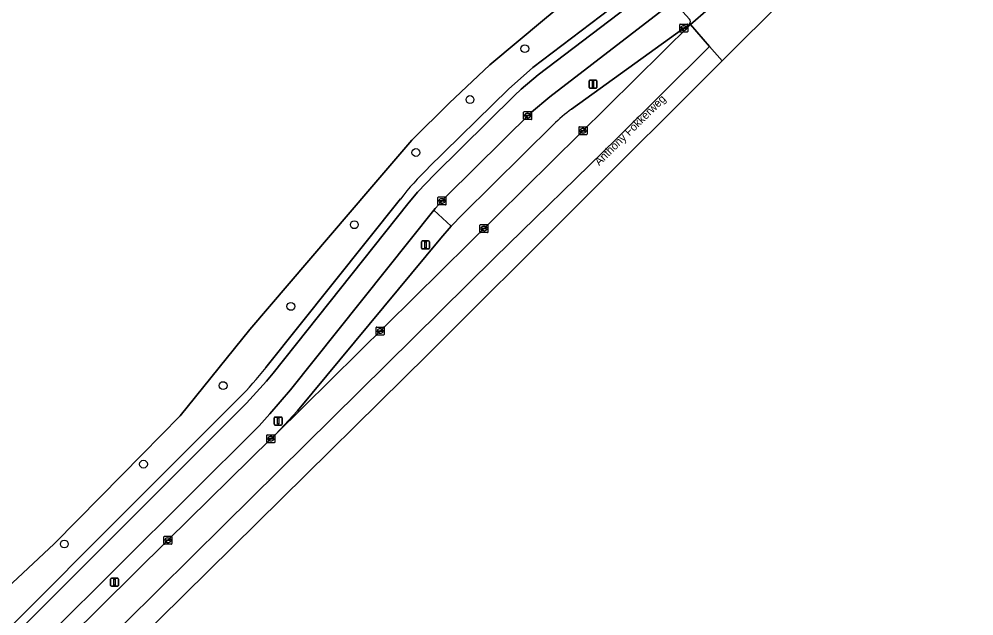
# Model space of a CAD drawing. Extents: x 157320 to 158835, y 386650 to 388491.
# Drawn here: x 158261 to 158380.4, y 386795.4 to 386870.1 of the extents above; entities that cross this region are included whole.
import ezdxf

# ---------------------------------------------------------------- set-up
doc = ezdxf.new("R2010")
doc.units = 0
for name, color, linetype in [('IMGEO_Berm_groen', 7, 'Continuous'), ('IMGEO_Boom', 7, 'Continuous'), ('IMGEO_Bouwland', 7, 'Continuous'), ('IMGEO_Fietspad_gesloten', 7, 'Continuous'), ('IMGEO_Grasland_overig', 7, 'Continuous'), ('IMGEO_Kolk', 7, 'Continuous'), ('IMGEO_Lichtmast', 7, 'Continuous'), ('IMGEO_Openbare_ruimte_label', 7, 'Continuous'), ('IMGEO_OVBaan_open', 7, 'Continuous'), ('IMGEO_Rijbaan_regionaal_gesloten', 7, 'Continuous'), ('IMGEO_Voetpad_open', 7, 'Continuous')]:
    doc.layers.add(name, color=color, linetype=linetype)

msp = doc.modelspace()

# ---------------------------------------------------------------- linework, layer by layer
at = {"layer": 'IMGEO_Berm_groen'}
msp.add_lwpolyline([(158292.51, 386817.6), (158293.08, 386818.13), (158295.82, 386821.08), (158313.75, 386842.66), (158315.04, 386844.17), (158312.86, 386846.16), (158294.96, 386823.72), (158292.37, 386820.71), (158291.06, 386819.23), (158247.07, 386775.47), (158248.3, 386773.88), (158248.45, 386774.04), (158252.57, 386778.18), (158267.21, 386792.63), (158279.64, 386804.91)], close=True, dxfattribs=at)
at = {"layer": 'IMGEO_Boom'}
for centre in [(158324.24, 386866.36), (158317.39, 386860), (158310.63, 386853.38), (158302.94, 386844.35), (158295.01, 386834.14), (158286.54, 386824.24), (158276.59, 386814.42), (158266.69, 386804.43)]:
    msp.add_circle(centre, 0.489, dxfattribs=at)
at = {"layer": 'IMGEO_Bouwland'}
msp.add_lwpolyline([(158181.71, 386843.44), (158180.07, 386842.58), (158234.95, 386779.48), (158235.86, 386778.22), (158242.43, 386783.42), (158246.35, 386786.77), (158250.86, 386790.58), (158258.2, 386797.76), (158265.42, 386804.47), (158271.23, 386810.34), (158276.43, 386815.61), (158281.18, 386820.45), (158289.87, 386831.24), (158304.89, 386848.81), (158310.12, 386854.92), (158314.8, 386859.54), (158319.87, 386864.35), (158326.72, 386870.06), (158334.43, 386876.45), (158305.33, 386908.57)], close=True, dxfattribs=at)
at = {"layer": 'IMGEO_Fietspad_gesloten'}
for points in [[(158339.23, 386873.27), (158325.93, 386863.1), (158323.81, 386861.32), (158322.94, 386860.5), (158312.94, 386850.65), (158310.82, 386848.42), (158309.61, 386846.95), (158292.79, 386825.79), (158291.98, 386824.79), (158289.48, 386822.03), (158246.51, 386779.1)], [(158247.07, 386775.47), (158291.06, 386819.23), (158292.37, 386820.71), (158294.96, 386823.72), (158312.86, 386846.16), (158313.05, 386846.38), (158314.4, 386847.88), (158325.08, 386858.44), (158327.39, 386860.36), (158342.56, 386872.04)]]:
    msp.add_lwpolyline(points, dxfattribs=at)
at = {"layer": 'IMGEO_Grasland_overig'}
for points in [[(158312.15, 386851.45), (158322.2, 386861.32), (158325.26, 386863.99), (158338.55, 386874.13), (158336.73, 386873.92), (158334.43, 386876.45), (158326.72, 386870.06), (158319.87, 386864.35), (158314.8, 386859.54), (158310.12, 386854.92), (158304.89, 386848.81), (158289.87, 386831.24), (158281.18, 386820.45), (158276.43, 386815.61), (158271.23, 386810.34), (158265.42, 386804.47), (158258.2, 386797.76)], [(158291.9, 386826.49), (158308.7, 386847.57)], [(158245.74, 386779.89), (158288.52, 386822.66)]]:
    msp.add_lwpolyline(points, dxfattribs=at)
for centre, radius, start, end in [((158338.86, 386824.25), 38.12, 134.4883, 142.285), ((158254.51, 386856.09), 47.69, 315.4981, 321.6337)]:
    msp.add_arc(centre, radius, start, end, dxfattribs=at)
at = {"layer": 'IMGEO_Kolk'}
for p, q in [((158343.6, 386868.51), (158343.6, 386869.36)), ((158343.68, 386869.44), (158344.53, 386869.44)), ((158344.53, 386868.43), (158343.68, 386868.43)), ((158343.86, 386868.93), (158343.86, 386868.94)), ((158343.9, 386868.98), (158344.3, 386868.98)), ((158344.3, 386868.89), (158343.9, 386868.89)), ((158344.09, 386869.21), (158344.12, 386869.21)), ((158344.11, 386868.66), (158344.09, 386868.66)), ((158344.35, 386868.94), (158344.35, 386868.93)), ((158344.6, 386869.36), (158344.6, 386868.51)), ((158324.1, 386857.57), (158324.1, 386858.42)), ((158324.18, 386858.5), (158325.03, 386858.5)), ((158324.36, 386857.99), (158324.36, 386858)), ((158324.4, 386858.04), (158324.8, 386858.04)), ((158324.8, 386857.95), (158324.4, 386857.95)), ((158324.59, 386858.28), (158324.62, 386858.28)), ((158324.61, 386857.72), (158324.59, 386857.72)), ((158324.85, 386858), (158324.85, 386857.99)), ((158325.1, 386858.42), (158325.1, 386857.57)), ((158325.03, 386857.5), (158324.18, 386857.5)), ((158331.02, 386855.68), (158331.02, 386856.53)), ((158331.09, 386856.6), (158331.95, 386856.6)), ((158332.02, 386856.53), (158332.02, 386855.68)), ((158331.95, 386855.6), (158331.09, 386855.6)), ((158331.28, 386856.1), (158331.28, 386856.11)), ((158331.32, 386856.15), (158331.72, 386856.15)), ((158331.71, 386856.06), (158331.32, 386856.06)), ((158331.53, 386855.82), (158331.5, 386855.82)), ((158331.51, 386856.38), (158331.53, 386856.38)), ((158331.76, 386856.11), (158331.76, 386856.1)), ((158313.39, 386846.9), (158313.39, 386847.75)), ((158313.47, 386847.83), (158314.32, 386847.83)), ((158313.65, 386847.32), (158313.65, 386847.33)), ((158313.69, 386847.37), (158314.09, 386847.37)), ((158314.09, 386847.28), (158313.69, 386847.28)), ((158313.88, 386847.61), (158313.91, 386847.61)), ((158313.9, 386847.05), (158313.88, 386847.05)), ((158314.14, 386847.33), (158314.14, 386847.32)), ((158314.39, 386847.75), (158314.39, 386846.9)), ((158314.32, 386846.83), (158313.47, 386846.83)), ((158318.64, 386843.45), (158318.64, 386844.3)), ((158318.72, 386844.38), (158319.57, 386844.38)), ((158319.57, 386843.38), (158318.72, 386843.38)), ((158318.9, 386843.87), (158318.9, 386843.88)), ((158318.94, 386843.92), (158319.34, 386843.92)), ((158319.34, 386843.83), (158318.94, 386843.83)), ((158319.13, 386844.16), (158319.16, 386844.16)), ((158319.15, 386843.6), (158319.13, 386843.6)), ((158319.39, 386843.88), (158319.39, 386843.87)), ((158319.64, 386844.3), (158319.64, 386843.45)), ((158305.67, 386830.63), (158305.67, 386831.49)), ((158305.74, 386831.56), (158306.6, 386831.56)), ((158306.67, 386831.49), (158306.67, 386830.63)), ((158306.6, 386830.56), (158305.74, 386830.56)), ((158305.93, 386831.05), (158305.93, 386831.07)), ((158305.97, 386831.1), (158306.37, 386831.1)), ((158306.36, 386831.02), (158305.97, 386831.02)), ((158306.18, 386830.78), (158306.15, 386830.78)), ((158306.16, 386831.34), (158306.18, 386831.34)), ((158306.41, 386831.07), (158306.41, 386831.05)), ((158292.01, 386817.18), (158292.01, 386818.03)), ((158292.09, 386818.1), (158292.94, 386818.1)), ((158292.94, 386817.1), (158292.09, 386817.1)), ((158292.27, 386817.6), (158292.27, 386817.61)), ((158292.31, 386817.65), (158292.71, 386817.65)), ((158292.71, 386817.56), (158292.31, 386817.56)), ((158292.5, 386817.88), (158292.53, 386817.88)), ((158292.52, 386817.32), (158292.5, 386817.32)), ((158292.76, 386817.61), (158292.76, 386817.6)), ((158293.01, 386818.03), (158293.01, 386817.18)), ((158279.14, 386804.49), (158279.14, 386805.34)), ((158279.22, 386805.41), (158280.07, 386805.41)), ((158279.63, 386805.19), (158279.65, 386805.19)), ((158280.14, 386805.34), (158280.14, 386804.49)), ((158280.07, 386804.41), (158279.22, 386804.41)), ((158279.4, 386804.91), (158279.4, 386804.92)), ((158279.44, 386804.96), (158279.84, 386804.96)), ((158279.84, 386804.87), (158279.44, 386804.87)), ((158279.65, 386804.63), (158279.63, 386804.63)), ((158279.88, 386804.92), (158279.88, 386804.91))]:
    msp.add_line(p, q, dxfattribs=at)
for points in [[(158343.6, 386868.51), (158343.6, 386869.36)], [(158343.68, 386869.44), (158344.53, 386869.44)], [(158344.53, 386868.43), (158343.68, 386868.43)], [(158344.6, 386869.36), (158344.6, 386868.51)], [(158324.1, 386857.57), (158324.1, 386858.42)], [(158324.18, 386858.5), (158325.03, 386858.5)], [(158325.1, 386858.42), (158325.1, 386857.57)], [(158325.03, 386857.5), (158324.18, 386857.5)], [(158331.02, 386855.68), (158331.02, 386856.53)], [(158331.09, 386856.6), (158331.95, 386856.6)], [(158332.02, 386856.53), (158332.02, 386855.68)], [(158331.95, 386855.6), (158331.09, 386855.6)], [(158313.39, 386846.9), (158313.39, 386847.75)], [(158313.47, 386847.83), (158314.32, 386847.83)], [(158314.39, 386847.75), (158314.39, 386846.9)], [(158314.32, 386846.83), (158313.47, 386846.83)], [(158318.64, 386843.45), (158318.64, 386844.3)], [(158318.72, 386844.38), (158319.57, 386844.38)], [(158319.57, 386843.38), (158318.72, 386843.38)], [(158319.64, 386844.3), (158319.64, 386843.45)], [(158305.67, 386830.63), (158305.67, 386831.49)], [(158305.74, 386831.56), (158306.6, 386831.56)], [(158306.67, 386831.49), (158306.67, 386830.63)], [(158306.6, 386830.56), (158305.74, 386830.56)], [(158292.01, 386817.18), (158292.01, 386818.03)], [(158292.09, 386818.1), (158292.94, 386818.1)], [(158292.94, 386817.1), (158292.09, 386817.1)], [(158293.01, 386818.03), (158293.01, 386817.18)], [(158279.14, 386804.49), (158279.14, 386805.34)], [(158279.22, 386805.41), (158280.07, 386805.41)], [(158280.14, 386805.34), (158280.14, 386804.49)], [(158280.07, 386804.41), (158279.22, 386804.41)]]:
    msp.add_lwpolyline(points, dxfattribs=at)
for centre, radius, start, end in [((158343.68, 386869.36), 0.0765, 91.552, 178.448), ((158343.68, 386869.36), 0.0765, 91.552, 178.448), ((158343.68, 386868.51), 0.0765, 181.552, 268.448), ((158343.68, 386868.51), 0.0765, 181.552, 268.448), ((158343.9, 386868.94), 0.0403, 85.8775, 175.7526), ((158343.9, 386868.93), 0.0366, 178.938, 274.7102), ((158344.31, 386868.94), 0.0386, 1.7309, 96.639), ((158344.3, 386868.93), 0.043, 264.8664, 352.4533), ((158344.53, 386869.36), 0.0765, 1.552, 88.448), ((158344.53, 386869.36), 0.0765, 1.552, 88.448), ((158344.53, 386868.51), 0.0765, 271.552, 358.448), ((158344.53, 386868.51), 0.0765, 271.552, 358.448), ((158324.18, 386858.42), 0.0765, 91.552, 178.448), ((158324.18, 386858.42), 0.0765, 91.552, 178.448), ((158324.4, 386858), 0.0403, 85.8775, 175.7526), ((158324.4, 386857.99), 0.0366, 178.938, 274.7102), ((158324.81, 386858), 0.0386, 1.7309, 96.639), ((158324.8, 386858), 0.043, 264.8664, 352.4533), ((158325.03, 386858.42), 0.0765, 1.552, 88.448), ((158325.03, 386858.42), 0.0765, 1.552, 88.448), ((158324.18, 386857.57), 0.0765, 181.552, 268.448), ((158324.18, 386857.57), 0.0765, 181.552, 268.448), ((158325.03, 386857.57), 0.0765, 271.552, 358.448), ((158325.03, 386857.57), 0.0765, 271.552, 358.448), ((158331.09, 386856.53), 0.0765, 91.552, 178.448), ((158331.09, 386856.53), 0.0765, 91.552, 178.448), ((158331.94, 386856.53), 0.0765, 1.552, 88.448), ((158331.94, 386856.53), 0.0765, 1.552, 88.448), ((158331.09, 386855.68), 0.0765, 181.552, 268.448), ((158331.09, 386855.68), 0.0765, 181.552, 268.448), ((158331.32, 386856.11), 0.0403, 85.8775, 175.7526), ((158331.31, 386856.1), 0.0366, 178.938, 274.7102), ((158331.72, 386856.1), 0.043, 264.8664, 352.4533), ((158331.72, 386856.11), 0.0386, 1.7309, 96.639), ((158331.94, 386855.68), 0.0765, 271.552, 358.448), ((158331.94, 386855.68), 0.0765, 271.552, 358.448), ((158313.47, 386847.75), 0.0765, 91.552, 178.448), ((158313.47, 386847.75), 0.0765, 91.552, 178.448), ((158313.69, 386847.33), 0.0403, 85.8775, 175.7526), ((158313.69, 386847.32), 0.0366, 178.938, 274.7102), ((158314.1, 386847.33), 0.0386, 1.7309, 96.639), ((158314.09, 386847.33), 0.043, 264.8664, 352.4533), ((158314.32, 386847.75), 0.0765, 1.552, 88.448), ((158314.32, 386847.75), 0.0765, 1.552, 88.448), ((158313.47, 386846.9), 0.0765, 181.552, 268.448), ((158313.47, 386846.9), 0.0765, 181.552, 268.448), ((158314.32, 386846.9), 0.0765, 271.552, 358.448), ((158314.32, 386846.9), 0.0765, 271.552, 358.448), ((158318.72, 386844.3), 0.0765, 91.552, 178.448), ((158318.72, 386844.3), 0.0765, 91.552, 178.448), ((158318.72, 386843.45), 0.0765, 181.552, 268.448), ((158318.72, 386843.45), 0.0765, 181.552, 268.448), ((158318.94, 386843.88), 0.0403, 85.8775, 175.7526), ((158318.94, 386843.87), 0.0366, 178.938, 274.7102), ((158319.35, 386843.88), 0.0386, 1.7309, 96.639), ((158319.34, 386843.88), 0.043, 264.8664, 352.4533), ((158319.57, 386844.3), 0.0765, 1.552, 88.448), ((158319.57, 386844.3), 0.0765, 1.552, 88.448), ((158319.57, 386843.45), 0.0765, 271.552, 358.448), ((158319.57, 386843.45), 0.0765, 271.552, 358.448), ((158305.74, 386831.48), 0.0765, 91.552, 178.448), ((158305.74, 386831.48), 0.0765, 91.552, 178.448), ((158306.59, 386831.48), 0.0765, 1.552, 88.448), ((158306.59, 386831.48), 0.0765, 1.552, 88.448), ((158305.74, 386830.64), 0.0765, 181.552, 268.448), ((158305.74, 386830.64), 0.0765, 181.552, 268.448), ((158305.97, 386831.06), 0.0403, 85.8775, 175.7526), ((158305.96, 386831.05), 0.0366, 178.938, 274.7102), ((158306.37, 386831.06), 0.043, 264.8664, 352.4533), ((158306.37, 386831.06), 0.0386, 1.7309, 96.639), ((158306.59, 386830.64), 0.0765, 271.552, 358.448), ((158306.59, 386830.64), 0.0765, 271.552, 358.448), ((158292.09, 386818.03), 0.0765, 91.552, 178.448), ((158292.09, 386818.03), 0.0765, 91.552, 178.448), ((158292.09, 386817.18), 0.0765, 181.552, 268.448), ((158292.09, 386817.18), 0.0765, 181.552, 268.448), ((158292.31, 386817.61), 0.0403, 85.8775, 175.7526), ((158292.31, 386817.6), 0.0366, 178.938, 274.7102), ((158292.72, 386817.61), 0.0386, 1.7309, 96.639), ((158292.71, 386817.6), 0.043, 264.8664, 352.4533), ((158292.94, 386818.03), 0.0765, 1.552, 88.448), ((158292.94, 386818.03), 0.0765, 1.552, 88.448), ((158292.94, 386817.18), 0.0765, 271.552, 358.448), ((158292.94, 386817.18), 0.0765, 271.552, 358.448), ((158279.22, 386805.34), 0.0765, 91.552, 178.448), ((158279.22, 386805.34), 0.0765, 91.552, 178.448), ((158280.07, 386805.34), 0.0765, 1.552, 88.448), ((158280.07, 386805.34), 0.0765, 1.552, 88.448), ((158279.22, 386804.49), 0.0765, 181.552, 268.448), ((158279.22, 386804.49), 0.0765, 181.552, 268.448), ((158279.44, 386804.92), 0.0403, 85.8775, 175.7526), ((158279.44, 386804.91), 0.0366, 178.938, 274.7102), ((158279.85, 386804.92), 0.0386, 1.7309, 96.639), ((158279.84, 386804.91), 0.043, 264.8664, 352.4533), ((158280.07, 386804.49), 0.0765, 271.552, 358.448), ((158280.07, 386804.49), 0.0765, 271.552, 358.448)]:
    msp.add_arc(centre, radius, start, end, dxfattribs=at)
for centre, major_axis, ratio, start_param, end_param in [((158344.09, 386868.93), (-0.387, 0.002), 0.722429, 4.712389, 7.853982), ((158344.11, 386868.93), (-0.39, 0.002), 0.717154, 1.570796, 4.712389), ((158324.59, 386858), (-0.387, 0.002), 0.722429, 4.712389, 7.853982), ((158324.61, 386858), (-0.39, 0.002), 0.717154, 1.570796, 4.712389), ((158331.51, 386856.1), (-0.387, 0.002), 0.722429, 4.712389, 7.853982), ((158331.53, 386856.1), (-0.39, 0.002), 0.717154, 1.570796, 4.712389), ((158313.88, 386847.33), (-0.387, 0.002), 0.722429, 4.712389, 7.853982), ((158313.9, 386847.33), (-0.39, 0.002), 0.717154, 1.570796, 4.712389), ((158319.13, 386843.88), (-0.387, 0.002), 0.722429, 4.712389, 7.853982), ((158319.15, 386843.88), (-0.39, 0.002), 0.717154, 1.570796, 4.712389), ((158306.16, 386831.06), (-0.387, 0.002), 0.722429, 4.712389, 7.853982), ((158306.18, 386831.06), (-0.39, 0.002), 0.717154, 1.570796, 4.712389), ((158292.5, 386817.6), (-0.387, 0.002), 0.722429, 4.712389, 7.853982), ((158292.52, 386817.6), (-0.39, 0.002), 0.717154, 1.570796, 4.712389), ((158279.63, 386804.91), (-0.387, 0.002), 0.722429, 4.712389, 7.853982), ((158279.65, 386804.91), (-0.39, 0.002), 0.717154, 1.570796, 4.712389)]:
    msp.add_ellipse(centre, major_axis=major_axis, ratio=ratio, start_param=start_param, end_param=end_param, dxfattribs=at)
at = {"layer": 'IMGEO_Lichtmast'}
for p, q in [((158332.37, 386862.43), (158333.16, 386862.43)), ((158333.16, 386862.43), (158332.37, 386862.43)), ((158332.27, 386861.53), (158332.27, 386862.33)), ((158332.27, 386862.33), (158332.27, 386861.53)), ((158333.16, 386861.43), (158332.37, 386861.43)), ((158332.37, 386861.43), (158333.16, 386861.43)), ((158333.26, 386862.33), (158333.26, 386861.53)), ((158333.26, 386861.53), (158333.26, 386862.33)), ((158311.33, 386841.43), (158311.33, 386842.23)), ((158311.33, 386842.23), (158311.33, 386841.43)), ((158311.43, 386842.33), (158312.22, 386842.33)), ((158312.22, 386842.33), (158311.43, 386842.33)), ((158312.32, 386842.23), (158312.32, 386841.43)), ((158312.32, 386841.43), (158312.32, 386842.23)), ((158312.22, 386841.33), (158311.43, 386841.33)), ((158311.43, 386841.33), (158312.22, 386841.33)), ((158292.92, 386819.41), (158292.92, 386820.21)), ((158292.92, 386820.21), (158292.92, 386819.41)), ((158293.02, 386820.31), (158293.81, 386820.31)), ((158293.81, 386820.31), (158293.02, 386820.31)), ((158293.91, 386820.21), (158293.91, 386819.41)), ((158293.91, 386819.41), (158293.91, 386820.21)), ((158293.81, 386819.31), (158293.02, 386819.31)), ((158293.02, 386819.31), (158293.81, 386819.31)), ((158272.48, 386799.26), (158272.48, 386800.06)), ((158272.48, 386800.06), (158272.48, 386799.26)), ((158272.58, 386800.16), (158273.37, 386800.16)), ((158273.37, 386800.16), (158272.58, 386800.16)), ((158273.47, 386800.06), (158273.47, 386799.26)), ((158273.47, 386799.26), (158273.47, 386800.06)), ((158273.37, 386799.16), (158272.58, 386799.16)), ((158272.58, 386799.16), (158273.37, 386799.16))]:
    msp.add_line(p, q, dxfattribs=at)
for points in [[(158332.69, 386862.3), (158332.84, 386862.3), (158332.84, 386861.55), (158332.69, 386861.55), (158332.69, 386862.3)], [(158311.75, 386842.2), (158311.9, 386842.2), (158311.9, 386841.45), (158311.75, 386841.45), (158311.75, 386842.2)], [(158293.34, 386820.19), (158293.49, 386820.19), (158293.49, 386819.44), (158293.34, 386819.44), (158293.34, 386820.19)], [(158272.9, 386800.04), (158273.05, 386800.04), (158273.05, 386799.29), (158272.9, 386799.29), (158272.9, 386800.04)]]:
    msp.add_lwpolyline(points, dxfattribs=at)
for centre, start, end in [((158332.37, 386862.33), 90, 180), ((158332.37, 386862.33), 90, 180), ((158333.16, 386862.33), 0, 90), ((158333.16, 386862.33), 360, 90), ((158332.37, 386861.53), 180, 270), ((158332.37, 386861.53), 180, 270), ((158333.16, 386861.53), 270, 0), ((158333.16, 386861.53), 270, 0), ((158311.43, 386842.23), 90, 180), ((158311.43, 386842.23), 90, 180), ((158312.22, 386842.23), 0, 90), ((158312.22, 386842.23), 360, 90), ((158311.43, 386841.43), 180, 270), ((158311.43, 386841.43), 180, 270), ((158312.22, 386841.43), 270, 0), ((158312.22, 386841.43), 270, 0), ((158293.02, 386820.21), 90, 180), ((158293.02, 386820.21), 90, 180), ((158293.81, 386820.21), 0, 90), ((158293.81, 386820.21), 360, 90), ((158293.02, 386819.41), 180, 270), ((158293.02, 386819.41), 180, 270), ((158293.81, 386819.41), 270, 0), ((158293.81, 386819.41), 270, 0), ((158272.58, 386800.06), 90, 180), ((158272.58, 386800.06), 90, 180), ((158272.58, 386799.26), 180, 270), ((158272.58, 386799.26), 180, 270), ((158273.37, 386800.06), 0, 90), ((158273.37, 386800.06), 360, 90), ((158273.37, 386799.26), 270, 0), ((158273.37, 386799.26), 270, 0)]:
    msp.add_arc(centre, 0.1, start, end, dxfattribs=at)
at = {"layer": 'IMGEO_OVBaan_open'}
for points in [[(158327.83, 386856.87), (158316.46, 386845.62), (158315.04, 386844.17), (158313.75, 386842.66), (158295.82, 386821.08), (158293.08, 386818.13), (158344.97, 386869.39)], [(158344.97, 386869.39), (158344.86, 386869.49), (158344.73, 386869.36), (158344.1, 386868.93), (158330.09, 386858.81)]]:
    msp.add_lwpolyline(points, dxfattribs=at)
msp.add_arc((158341.79, 386842.88), 19.77, 126.322, 134.9517, dxfattribs=at)
at = {"layer": 'IMGEO_Rijbaan_regionaal_gesloten'}
for points in [[(158348.92, 386864.83), (158380.37, 386896.19), (158379.17, 386897.42), (158376.82, 386899.78), (158352.45, 386875.99), (158347.18, 386871.3), (158344.97, 386869.39), (158347.34, 386866.65)], [(158130.56, 386652.21), (158132, 386650.44), (158312.16, 386828.18), (158348.92, 386864.83), (158347.34, 386866.65), (158335.71, 386855.08), (158320.48, 386840.25), (158286.69, 386806.82), (158261.92, 386782.32), (158241.47, 386762.08), (158200.32, 386721.36), (158181.84, 386703.08), (158161.95, 386683.39), (158151.06, 386672.76)]]:
    msp.add_lwpolyline(points, close=True, dxfattribs=at)
msp.add_lwpolyline([(158241.47, 386762.08), (158261.92, 386782.32), (158286.69, 386806.82), (158320.48, 386840.25), (158335.71, 386855.08), (158347.34, 386866.65), (158344.97, 386869.39), (158293.08, 386818.13), (158292.51, 386817.6), (158279.64, 386804.91), (158267.21, 386792.63), (158252.57, 386778.18)], dxfattribs=at)
at = {"layer": 'IMGEO_Voetpad_open'}
for points in [[(158246.51, 386779.1), (158289.48, 386822.03), (158291.98, 386824.79), (158292.79, 386825.79), (158309.61, 386846.95), (158310.82, 386848.42), (158312.94, 386850.65), (158322.94, 386860.5), (158323.81, 386861.32), (158325.93, 386863.1), (158339.23, 386873.27), (158338.55, 386874.13), (158325.26, 386863.99), (158322.2, 386861.32), (158312.15, 386851.45)], [(158342.56, 386872.04), (158327.39, 386860.36), (158325.08, 386858.44), (158314.4, 386847.88), (158313.05, 386846.38), (158312.86, 386846.16), (158315.04, 386844.17), (158316.46, 386845.62), (158327.83, 386856.87)], [(158343.14, 386871.9), (158344.83, 386870.06)], [(158344.83, 386870.06), (158343.14, 386871.9)], [(158344.86, 386869.49), (158344.97, 386869.39), (158347.18, 386871.3)], [(158330.09, 386858.81), (158344.1, 386868.93), (158344.73, 386869.36), (158344.86, 386869.49)], [(158308.7, 386847.57), (158291.9, 386826.49)], [(158288.52, 386822.66), (158245.74, 386779.89), (158227.5, 386761.86), (158215.51, 386750), (158164.69, 386699.74), (158163.33, 386698.35), (158162.76, 386698.11), (158144.91, 386680.58), (158144.71, 386680.38), (158138.93, 386674.66), (158136.68, 386672.43), (158124.15, 386660.05), (158125.08, 386658.92)]]:
    msp.add_lwpolyline(points, dxfattribs=at)
for centre, radius, start, end in [((158344.48, 386869.76), 0.462, 323.9264, 41.2426), ((158344.48, 386869.76), 0.462, 323.9264, 41.2426), ((158341.79, 386842.88), 19.77, 126.322, 134.9517), ((158338.86, 386824.25), 38.12, 134.4883, 142.285), ((158254.51, 386856.09), 47.69, 315.4981, 321.6337)]:
    msp.add_arc(centre, radius, start, end, dxfattribs=at)

# ---------------------------------------------------------------- texts
at = {"layer": 'IMGEO_Openbare_ruimte_label'}
msp.add_text('Anthony Fokkerweg', height=1, rotation=44.6356, dxfattribs=at).set_placement((158333.54, 386851.68))

doc.saveas('drawing.dxf')
